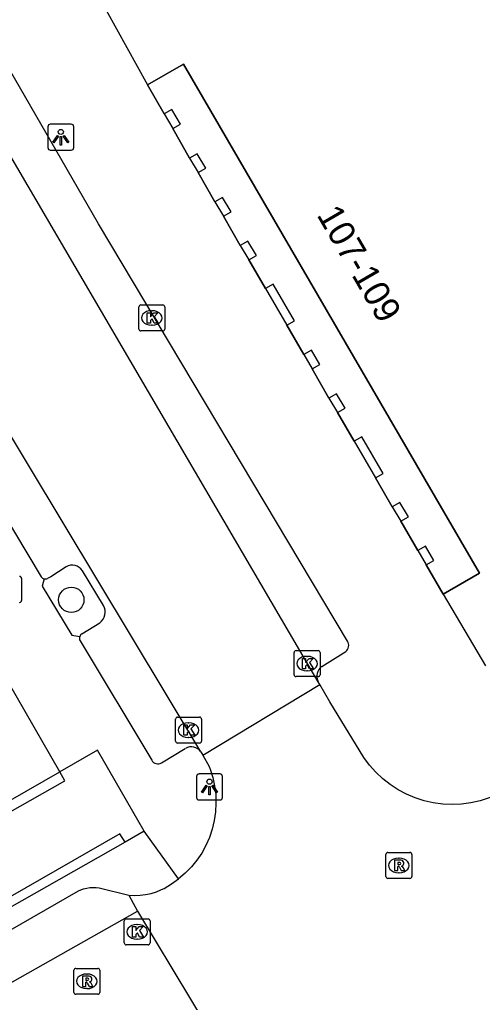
# Model space of a CAD drawing. Extents: x 160379 to 161131, y 383940 to 384849.
# Drawn here: x 160867.69 to 160885.53, y 384191.6 to 384229.46 of the extents above; entities that cross this region are included whole.
import ezdxf

# ---------------------------------------------------------------- set-up
doc = ezdxf.new("R2010")
doc.units = 0
for name, color, linetype in [('IMGEO_Boom', 7, 'Continuous'), ('IMGEO_Brandkraan', 7, 'Continuous'), ('IMGEO_Haag', 7, 'Continuous'), ('IMGEO_Kolk', 7, 'Continuous'), ('IMGEO_Lichtpunt', 7, 'Continuous'), ('IMGEO_Pand', 7, 'Continuous'), ('IMGEO_Pand_nummerreeks', 7, 'Continuous'), ('IMGEO_Pand_overbouw', 7, 'Continuous'), ('IMGEO_Parkeervlak_open', 7, 'Continuous'), ('IMGEO_Rijbaan_lokaal_open', 7, 'Continuous'), ('IMGEO_Rioolput', 7, 'Continuous'), ('IMGEO_Voetpad_open', 7, 'Continuous')]:
    doc.layers.add(name, color=color, linetype=linetype)

msp = doc.modelspace()

# ---------------------------------------------------------------- linework, layer by layer
at = {"layer": 'IMGEO_Boom'}
msp.add_circle((160869.679, 384207.104), 0.489, dxfattribs=at)
at = {"layer": 'IMGEO_Brandkraan'}
msp.add_line((160867.761, 384207.931), (160867.761, 384207.079), dxfattribs=at)
msp.add_lwpolyline([(160867.761, 384207.931), (160867.761, 384207.079)], dxfattribs=at)
for centre, start, end in [((160867.685, 384207.929), 1.552, 88.448), ((160867.685, 384207.929), 1.552, 88.448), ((160867.685, 384207.081), 271.552, 358.448), ((160867.685, 384207.081), 271.552, 358.448)]:
    msp.add_arc(centre, 0.0765, start, end, dxfattribs=at)
at = {"layer": 'IMGEO_Haag'}
msp.add_lwpolyline([(160871.75, 384197.765), (160871.554, 384198.085), (160854.804, 384188.485), (160853.97, 384188.086), (160852.282, 384188.122), (160852.79, 384190.699), (160869.431, 384200.136), (160869.239, 384200.482)], dxfattribs=at)
at = {"layer": 'IMGEO_Kolk'}
for p, q in [((160872.282, 384217.538), (160872.282, 384218.39)), ((160872.357, 384218.464), (160873.209, 384218.464)), ((160872.77, 384218.244), (160872.795, 384218.244)), ((160873.283, 384218.39), (160873.283, 384217.538)), ((160873.209, 384217.464), (160872.357, 384217.464)), ((160872.793, 384217.684), (160872.768, 384217.684)), ((160878.269, 384204.219), (160878.269, 384205.071)), ((160878.344, 384205.145), (160879.196, 384205.145)), ((160878.757, 384204.925), (160878.782, 384204.925)), ((160879.27, 384205.071), (160879.27, 384204.219)), ((160879.196, 384204.145), (160878.344, 384204.145)), ((160878.78, 384204.365), (160878.755, 384204.365)), ((160873.699, 384201.657), (160873.699, 384202.509)), ((160873.774, 384202.583), (160874.626, 384202.583)), ((160874.187, 384202.363), (160874.212, 384202.363)), ((160874.7, 384202.509), (160874.7, 384201.657)), ((160874.626, 384201.583), (160873.774, 384201.583)), ((160874.21, 384201.803), (160874.185, 384201.803)), ((160871.717, 384193.885), (160871.717, 384194.737)), ((160871.792, 384194.811), (160872.644, 384194.811)), ((160872.718, 384194.737), (160872.718, 384193.885)), ((160872.205, 384194.591), (160872.23, 384194.591)), ((160872.228, 384194.031), (160872.203, 384194.031)), ((160872.644, 384193.811), (160871.792, 384193.811))]:
    msp.add_line(p, q, dxfattribs=at)
for points in [[(160872.282, 384217.538), (160872.282, 384218.39)], [(160872.357, 384218.464), (160873.209, 384218.464)], [(160872.603, 384218.164), (160872.726, 384218.164), (160872.726, 384218.013), (160872.856, 384218.164), (160873.02, 384218.164), (160872.874, 384218.013), (160873.027, 384217.764), (160872.875, 384217.764), (160872.79, 384217.928), (160872.726, 384217.861), (160872.726, 384217.764), (160872.603, 384217.764), (160872.603, 384218.164)], [(160873.283, 384218.39), (160873.283, 384217.538)], [(160873.209, 384217.464), (160872.357, 384217.464)], [(160878.269, 384204.219), (160878.269, 384205.071)], [(160878.344, 384205.145), (160879.196, 384205.145)], [(160879.27, 384205.071), (160879.27, 384204.219)], [(160878.59, 384204.845), (160878.713, 384204.845), (160878.713, 384204.694), (160878.843, 384204.845), (160879.007, 384204.845), (160878.861, 384204.694), (160879.014, 384204.445), (160878.862, 384204.445), (160878.777, 384204.609), (160878.713, 384204.542), (160878.713, 384204.445), (160878.59, 384204.445), (160878.59, 384204.845)], [(160879.196, 384204.145), (160878.344, 384204.145)], [(160873.699, 384201.657), (160873.699, 384202.509)], [(160873.774, 384202.583), (160874.626, 384202.583)], [(160874.02, 384202.283), (160874.143, 384202.283), (160874.143, 384202.132), (160874.273, 384202.283), (160874.437, 384202.283), (160874.291, 384202.132), (160874.444, 384201.883), (160874.292, 384201.883), (160874.207, 384202.047), (160874.143, 384201.98), (160874.143, 384201.883), (160874.02, 384201.883), (160874.02, 384202.283)], [(160874.7, 384202.509), (160874.7, 384201.657)], [(160874.626, 384201.583), (160873.774, 384201.583)], [(160871.717, 384193.885), (160871.717, 384194.737)], [(160871.792, 384194.811), (160872.644, 384194.811)], [(160872.718, 384194.737), (160872.718, 384193.885)], [(160872.038, 384194.511), (160872.161, 384194.511), (160872.161, 384194.36), (160872.291, 384194.511), (160872.455, 384194.511), (160872.309, 384194.36), (160872.462, 384194.111), (160872.31, 384194.111), (160872.225, 384194.275), (160872.161, 384194.208), (160872.161, 384194.111), (160872.038, 384194.111), (160872.038, 384194.511)], [(160872.644, 384193.811), (160871.792, 384193.811)]]:
    msp.add_lwpolyline(points, dxfattribs=at)
for centre, start, end in [((160872.359, 384218.388), 91.552, 178.448), ((160872.359, 384218.388), 91.552, 178.448), ((160873.207, 384218.388), 1.552, 88.448), ((160873.207, 384218.388), 1.552, 88.448), ((160872.359, 384217.54), 181.552, 268.448), ((160872.359, 384217.54), 181.552, 268.448), ((160873.207, 384217.54), 271.552, 358.448), ((160873.207, 384217.54), 271.552, 358.448), ((160878.346, 384205.069), 91.552, 178.448), ((160878.346, 384205.069), 91.552, 178.448), ((160879.194, 384205.069), 1.552, 88.448), ((160879.194, 384205.069), 1.552, 88.448), ((160878.346, 384204.221), 181.552, 268.448), ((160878.346, 384204.221), 181.552, 268.448), ((160879.194, 384204.221), 271.552, 358.448), ((160879.194, 384204.221), 271.552, 358.448), ((160873.776, 384202.507), 91.552, 178.448), ((160873.776, 384202.507), 91.552, 178.448), ((160874.624, 384202.507), 1.552, 88.448), ((160874.624, 384202.507), 1.552, 88.448), ((160873.776, 384201.659), 181.552, 268.448), ((160873.776, 384201.659), 181.552, 268.448), ((160874.624, 384201.659), 271.552, 358.448), ((160874.624, 384201.659), 271.552, 358.448), ((160871.794, 384194.735), 91.552, 178.448), ((160871.794, 384194.735), 91.552, 178.448), ((160872.642, 384194.735), 1.552, 88.448), ((160872.642, 384194.735), 1.552, 88.448), ((160871.794, 384193.887), 181.552, 268.448), ((160871.794, 384193.887), 181.552, 268.448), ((160872.642, 384193.887), 271.552, 358.448), ((160872.642, 384193.887), 271.552, 358.448)]:
    msp.add_arc(centre, 0.0765, start, end, dxfattribs=at)
for centre, major_axis, ratio, start_param, end_param in [((160872.769, 384217.964), (-0.387, 0.002), 0.722429, 4.712389, 7.853982), ((160872.794, 384217.964), (-0.39, 0.002), 0.717154, 1.570796, 4.712389), ((160878.756, 384204.645), (-0.387, 0.002), 0.722429, 4.712389, 7.853982), ((160878.781, 384204.645), (-0.39, 0.002), 0.717154, 1.570796, 4.712389), ((160874.186, 384202.083), (-0.387, 0.002), 0.722429, 4.712389, 7.853982), ((160874.211, 384202.083), (-0.39, 0.002), 0.717154, 1.570796, 4.712389), ((160872.204, 384194.311), (-0.387, 0.002), 0.722429, 4.712389, 7.853982), ((160872.229, 384194.311), (-0.39, 0.002), 0.717154, 1.570796, 4.712389)]:
    msp.add_ellipse(centre, major_axis=major_axis, ratio=ratio, start_param=start_param, end_param=end_param, dxfattribs=at)
at = {"layer": 'IMGEO_Lichtpunt'}
for p, q in [((160868.776, 384225.333), (160868.776, 384224.526)), ((160868.776, 384225.333), (160868.776, 384224.526)), ((160869.678, 384225.428), (160868.87, 384225.428)), ((160869.678, 384225.428), (160868.87, 384225.428)), ((160869.772, 384224.526), (160869.772, 384225.333)), ((160869.772, 384224.526), (160869.772, 384225.333)), ((160868.87, 384224.432), (160869.678, 384224.432)), ((160868.87, 384224.432), (160869.678, 384224.432)), ((160875.412, 384200.393), (160874.604, 384200.393)), ((160875.412, 384200.393), (160874.604, 384200.393)), ((160874.51, 384200.298), (160874.51, 384199.491)), ((160874.51, 384200.298), (160874.51, 384199.491)), ((160875.506, 384199.491), (160875.506, 384200.298)), ((160875.506, 384199.491), (160875.506, 384200.298)), ((160874.604, 384199.397), (160875.412, 384199.397)), ((160874.604, 384199.397), (160875.412, 384199.397))]:
    msp.add_line(p, q, dxfattribs=at)
for points in [[(160869.15, 384224.997), (160869.189, 384224.969), (160869.001, 384224.707), (160868.963, 384224.734), (160869.15, 384224.997)], [(160869.252, 384224.949), (160869.299, 384224.949), (160869.299, 384224.627), (160869.252, 384224.627), (160869.252, 384224.949)], [(160869.362, 384224.969), (160869.4, 384224.996), (160869.587, 384224.734), (160869.548, 384224.706), (160869.362, 384224.969)], [(160874.884, 384199.962), (160874.923, 384199.934), (160874.735, 384199.672), (160874.697, 384199.699), (160874.884, 384199.962)], [(160875.096, 384199.934), (160875.134, 384199.961), (160875.321, 384199.699), (160875.282, 384199.671), (160875.096, 384199.934)], [(160874.986, 384199.914), (160875.033, 384199.914), (160875.033, 384199.592), (160874.986, 384199.592), (160874.986, 384199.914)]]:
    msp.add_lwpolyline(points, dxfattribs=at)
for centre in [(160869.275, 384225.131), (160875.009, 384200.096)]:
    msp.add_circle(centre, 0.0994, dxfattribs=at)
for centre, start, end in [((160868.87, 384225.333), 90, 180), ((160868.87, 384225.333), 90, 180), ((160869.678, 384225.333), 0, 90), ((160869.678, 384225.333), 0, 90), ((160868.87, 384224.526), 180, 270), ((160868.87, 384224.526), 180, 270), ((160869.678, 384224.526), 270, 0), ((160869.678, 384224.526), 270, 360), ((160874.604, 384200.298), 90, 180), ((160874.604, 384200.298), 90, 180), ((160875.412, 384200.298), 0, 90), ((160875.412, 384200.298), 0, 90), ((160874.604, 384199.491), 180, 270), ((160874.604, 384199.491), 180, 270), ((160875.412, 384199.491), 270, 0), ((160875.412, 384199.491), 270, 360)]:
    msp.add_arc(centre, 0.0946, start, end, dxfattribs=at)
at = {"layer": 'IMGEO_Pand'}
for points in [[(160870.628, 384230.556), (160872.611, 384226.95)], [(160872.611, 384226.95), (160874.008, 384227.747), (160885.41, 384208.137), (160884.021, 384207.323)], [(160873.588, 384225.269), (160873.884, 384225.436), (160873.554, 384225.99), (160873.258, 384225.823)], [(160873.258, 384225.823), (160873.588, 384225.269)], [(160874.571, 384223.567), (160874.867, 384223.734), (160874.537, 384224.289), (160874.241, 384224.122)], [(160874.241, 384224.122), (160874.571, 384223.567)], [(160875.542, 384221.89), (160875.838, 384222.057), (160875.508, 384222.611), (160875.212, 384222.444)], [(160875.212, 384222.444), (160875.542, 384221.89)], [(160876.522, 384220.206), (160876.818, 384220.373), (160876.488, 384220.927), (160876.192, 384220.76)], [(160876.192, 384220.76), (160876.522, 384220.206)], [(160877.987, 384217.683), (160878.283, 384217.85), (160877.461, 384219.264), (160877.165, 384219.097)], [(160877.165, 384219.097), (160877.987, 384217.683)], [(160878.968, 384216.004), (160879.265, 384216.171), (160878.935, 384216.725), (160878.638, 384216.558)], [(160878.638, 384216.558), (160878.968, 384216.004)], [(160879.94, 384214.321), (160880.236, 384214.488), (160879.906, 384215.042), (160879.61, 384214.875)], [(160879.61, 384214.875), (160879.94, 384214.321)], [(160881.403, 384211.804), (160881.699, 384211.971), (160880.877, 384213.385), (160880.581, 384213.218)], [(160880.581, 384213.218), (160881.403, 384211.804)], [(160882.379, 384210.132), (160882.675, 384210.3), (160882.345, 384210.854), (160882.049, 384210.687)], [(160882.049, 384210.687), (160882.379, 384210.132)], [(160883.364, 384208.455), (160883.66, 384208.622), (160883.331, 384209.176), (160883.034, 384209.009)], [(160883.034, 384209.009), (160883.364, 384208.455)], [(160884.021, 384207.323), (160885.643, 384204.556)]]:
    msp.add_lwpolyline(points, dxfattribs=at)
at = {"layer": 'IMGEO_Pand_overbouw'}
msp.add_lwpolyline([(160874.008, 384227.747), (160872.611, 384226.95), (160873.258, 384225.823), (160873.588, 384225.269), (160874.241, 384224.122), (160874.571, 384223.567), (160875.212, 384222.444), (160875.542, 384221.89), (160876.192, 384220.76), (160876.522, 384220.206), (160877.165, 384219.097), (160877.987, 384217.683), (160878.638, 384216.558), (160878.968, 384216.004), (160879.61, 384214.875), (160879.94, 384214.321), (160880.581, 384213.218), (160881.403, 384211.804), (160882.049, 384210.687), (160882.379, 384210.132), (160883.034, 384209.009), (160883.364, 384208.455), (160884.021, 384207.323), (160885.41, 384208.137)], close=True, dxfattribs=at)
at = {"layer": 'IMGEO_Parkeervlak_open'}
for points in [[(160869.477, 384208.374), (160868.893, 384207.99), (160868.764, 384207.923)], [(160870.922, 384206.88), (160870.108, 384208.223)], [(160870.08, 384205.799), (160870.775, 384206.222)]]:
    msp.add_lwpolyline(points, dxfattribs=at)
for centre, radius, start, end in [((160869.712, 384207.963), 0.474, 33.3401, 119.744), ((160868.679, 384208.127), 0.221, 257.937, 292.5307), ((160870.488, 384206.631), 0.5, 304.991, 29.8223), ((160870.217, 384205.618), 0.227, 127.0893, 161.2354)]:
    msp.add_arc(centre, radius, start, end, dxfattribs=at)
at = {"layer": 'IMGEO_Rijbaan_lokaal_open'}
for points in [[(160879.197, 384203.944), (160858.945, 384238.524), (160855.862, 384243.943)], [(160874.677, 384201.242), (160866.674, 384214.519), (160851.399, 384241.272)], [(160874.745, 384201.123), (160879.26, 384203.835)], [(160879.26, 384203.835), (160879.197, 384203.944)], [(160888.276, 384200.778), (160886.486, 384199.819), (160886.446, 384199.794), (160886.125, 384199.621), (160885.789, 384199.478), (160885.443, 384199.365), (160885.087, 384199.283), (160884.726, 384199.233), (160884.362, 384199.216), (160883.998, 384199.232), (160883.636, 384199.28), (160883.28, 384199.36), (160882.933, 384199.472), (160882.598, 384199.614), (160882.276, 384199.785), (160881.971, 384199.985), (160881.685, 384200.211), (160881.42, 384200.462), (160881.179, 384200.735), (160880.963, 384201.029), (160879.642, 384203.175), (160879.26, 384203.835)], [(160874.745, 384201.123), (160874.997, 384200.678), (160875.033, 384200.582), (160875.133, 384200.262), (160875.204, 384199.933), (160875.245, 384199.6), (160875.256, 384199.264), (160875.237, 384198.929), (160875.189, 384198.596), (160875.111, 384198.27), (160875.004, 384197.951), (160874.869, 384197.644), (160874.707, 384197.349), (160874.519, 384197.071), (160874.307, 384196.81), (160874.073, 384196.569), (160873.818, 384196.35)], [(160874.677, 384201.242), (160874.745, 384201.123)], [(160871.895, 384195.725), (160872.111, 384195.713), (160872.328, 384195.72), (160872.543, 384195.746), (160872.755, 384195.792), (160872.961, 384195.856), (160873.162, 384195.939), (160873.255, 384195.985), (160873.545, 384196.155), (160873.818, 384196.35)], [(160871.895, 384195.725), (160872.226, 384195.111)], [(160859.628, 384187.997), (160872.226, 384195.111)], [(160872.226, 384195.111), (160874.951, 384190.587)]]:
    msp.add_lwpolyline(points, dxfattribs=at)
at = {"layer": 'IMGEO_Rioolput'}
for p, q in [((160881.807, 384196.444), (160881.807, 384197.296)), ((160881.882, 384197.37), (160882.734, 384197.37)), ((160882.808, 384197.296), (160882.808, 384196.444)), ((160882.295, 384197.15), (160882.32, 384197.15)), ((160882.318, 384196.59), (160882.293, 384196.59)), ((160882.734, 384196.37), (160881.882, 384196.37)), ((160869.776, 384191.979), (160869.776, 384192.831)), ((160869.851, 384192.905), (160870.703, 384192.905)), ((160870.777, 384192.831), (160870.777, 384191.979)), ((160870.264, 384192.685), (160870.289, 384192.685)), ((160870.287, 384192.125), (160870.262, 384192.125)), ((160870.703, 384191.905), (160869.851, 384191.905))]:
    msp.add_line(p, q, dxfattribs=at)
for points in [[(160881.807, 384196.444), (160881.807, 384197.296)], [(160881.882, 384197.37), (160882.734, 384197.37)], [(160882.808, 384197.296), (160882.808, 384196.444)], [(160882.396, 384197.068), (160882.144, 384197.07), (160882.144, 384196.67)], [(160882.322, 384196.989), (160882.268, 384196.989), (160882.268, 384196.908)], [(160882.268, 384196.908), (160882.32, 384196.908)], [(160882.144, 384196.67), (160882.268, 384196.67), (160882.268, 384196.832), (160882.279, 384196.832)], [(160882.326, 384196.803), (160882.397, 384196.67), (160882.537, 384196.67), (160882.472, 384196.796)], [(160882.734, 384196.37), (160881.882, 384196.37)], [(160869.776, 384191.979), (160869.776, 384192.831)], [(160869.851, 384192.905), (160870.703, 384192.905)], [(160870.777, 384192.831), (160870.777, 384191.979)], [(160870.365, 384192.603), (160870.113, 384192.605), (160870.113, 384192.205)], [(160870.113, 384192.205), (160870.237, 384192.205), (160870.237, 384192.367), (160870.248, 384192.367)], [(160870.291, 384192.524), (160870.237, 384192.524), (160870.237, 384192.443)], [(160870.237, 384192.443), (160870.289, 384192.443)], [(160870.295, 384192.338), (160870.366, 384192.205), (160870.506, 384192.205), (160870.441, 384192.331)], [(160870.703, 384191.905), (160869.851, 384191.905)]]:
    msp.add_lwpolyline(points, dxfattribs=at)
for centre, radius, start, end in [((160881.884, 384197.294), 0.0765, 91.552, 178.448), ((160881.884, 384197.294), 0.0765, 91.552, 178.448), ((160882.732, 384197.294), 0.0765, 1.552, 88.448), ((160882.732, 384197.294), 0.0765, 1.552, 88.448), ((160882.304, 384197.097), 0.19, 274.7715, 282.9687), ((160882.328, 384196.893), 0.0964, 77.0061, 93.1865), ((160882.342, 384196.95), 0.0378, 276.6634, 79.6772), ((160882.395, 384196.958), 0.109, 350.3612, 89.416), ((160882.393, 384196.958), 0.112, 277.5842, 350.9817), ((160882.278, 384196.779), 0.0533, 26.0293, 88.6989), ((160882.377, 384196.743), 0.108, 29.5134, 73.7905), ((160881.884, 384196.446), 0.0765, 181.552, 268.448), ((160881.884, 384196.446), 0.0765, 181.552, 268.448), ((160882.732, 384196.446), 0.0765, 271.552, 358.448), ((160882.732, 384196.446), 0.0765, 271.552, 358.448), ((160869.853, 384192.829), 0.0765, 91.552, 178.448), ((160869.853, 384192.829), 0.0765, 91.552, 178.448), ((160870.701, 384192.829), 0.0765, 1.552, 88.448), ((160870.701, 384192.829), 0.0765, 1.552, 88.448), ((160870.247, 384192.314), 0.0533, 26.0293, 88.6989), ((160870.273, 384192.632), 0.19, 274.7715, 282.9687), ((160870.297, 384192.428), 0.0964, 77.0061, 93.1865), ((160870.311, 384192.485), 0.0378, 276.6634, 79.6772), ((160870.364, 384192.493), 0.109, 350.3612, 89.416), ((160870.362, 384192.493), 0.112, 277.5842, 350.9817), ((160870.346, 384192.278), 0.108, 29.5134, 73.7905), ((160869.853, 384191.981), 0.0765, 181.552, 268.448), ((160869.853, 384191.981), 0.0765, 181.552, 268.448), ((160870.701, 384191.981), 0.0765, 271.552, 358.448), ((160870.701, 384191.981), 0.0765, 271.552, 358.448)]:
    msp.add_arc(centre, radius, start, end, dxfattribs=at)
for centre, major_axis, ratio, start_param, end_param in [((160882.294, 384196.87), (-0.387, 0.002), 0.722429, 4.712389, 7.853982), ((160882.319, 384196.87), (-0.39, 0.002), 0.717154, 1.570796, 4.712389), ((160870.263, 384192.405), (-0.387, 0.002), 0.722429, 4.712389, 7.853982), ((160870.288, 384192.405), (-0.39, 0.002), 0.717154, 1.570796, 4.712389)]:
    msp.add_ellipse(centre, major_axis=major_axis, ratio=ratio, start_param=start_param, end_param=end_param, dxfattribs=at)
at = {"layer": 'IMGEO_Voetpad_open'}
for points in [[(160880.332, 384205.516), (160870.733, 384221.584), (160860.47, 384239.358), (160858.111, 384243.568), (160858.09, 384243.602), (160857.716, 384244.216)], [(160873.258, 384225.823), (160872.611, 384226.95)], [(160874.241, 384224.122), (160873.588, 384225.269)], [(160875.212, 384222.444), (160874.571, 384223.567)], [(160859.998, 384222.609), (160860.267, 384222.122), (160864.469, 384214.751), (160868.515, 384207.985)], [(160876.192, 384220.76), (160875.542, 384221.89)], [(160877.165, 384219.097), (160876.522, 384220.206)], [(160878.638, 384216.558), (160877.987, 384217.683)], [(160879.61, 384214.875), (160878.968, 384216.004)], [(160880.581, 384213.218), (160879.94, 384214.321)], [(160882.049, 384210.687), (160881.403, 384211.804)], [(160883.034, 384209.009), (160882.379, 384210.132)], [(160884.021, 384207.323), (160883.364, 384208.455)], [(160868.633, 384207.911), (160868.56, 384207.635), (160869.7, 384205.744), (160870.002, 384205.691)], [(160870.015, 384205.523), (160872.784, 384200.921)], [(160879.34, 384204.541), (160880.258, 384205.107)], [(160869.239, 384200.482), (160866.899, 384204.525)], [(160872.494, 384198.187), (160870.686, 384201.311), (160869.239, 384200.482)], [(160873.16, 384200.829), (160874.075, 384201.376)], [(160871.75, 384197.765), (160860.176, 384191.2), (160854.079, 384187.84), (160851.951, 384187.892), (160852.51, 384190.896), (160858.924, 384194.572), (160869.239, 384200.482)], [(160872.494, 384198.187), (160871.75, 384197.765)], [(160873.818, 384196.35), (160872.494, 384198.187)], [(160861.189, 384190.861), (160869.958, 384195.892), (160870.04, 384195.928), (160870.155, 384195.968), (160870.272, 384195.998), (160870.392, 384196.017), (160870.513, 384196.025), (160870.634, 384196.022), (160870.755, 384196.009), (160871.895, 384195.725)]]:
    msp.add_lwpolyline(points, dxfattribs=at)
for centre, radius, start, end in [((160868.681, 384208.119), 0.214, 218.8983, 256.9165), ((160870.214, 384205.623), 0.223, 162.2264, 206.6231), ((160880.048, 384205.356), 0.326, 310.1372, 29.3517), ((160879.63, 384204.156), 0.482, 126.9936, 206.0658), ((160874.305, 384200.989), 0.45, 34.2261, 120.676), ((160873.013, 384201.044), 0.26, 208.2596, 304.2423)]:
    msp.add_arc(centre, radius, start, end, dxfattribs=at)

# ---------------------------------------------------------------- texts
at = {"layer": 'IMGEO_Pand_nummerreeks'}
msp.add_text('107-109', height=1, rotation=300.1775, dxfattribs=at).set_placement((160879.121, 384221.937))

doc.saveas('drawing.dxf')
